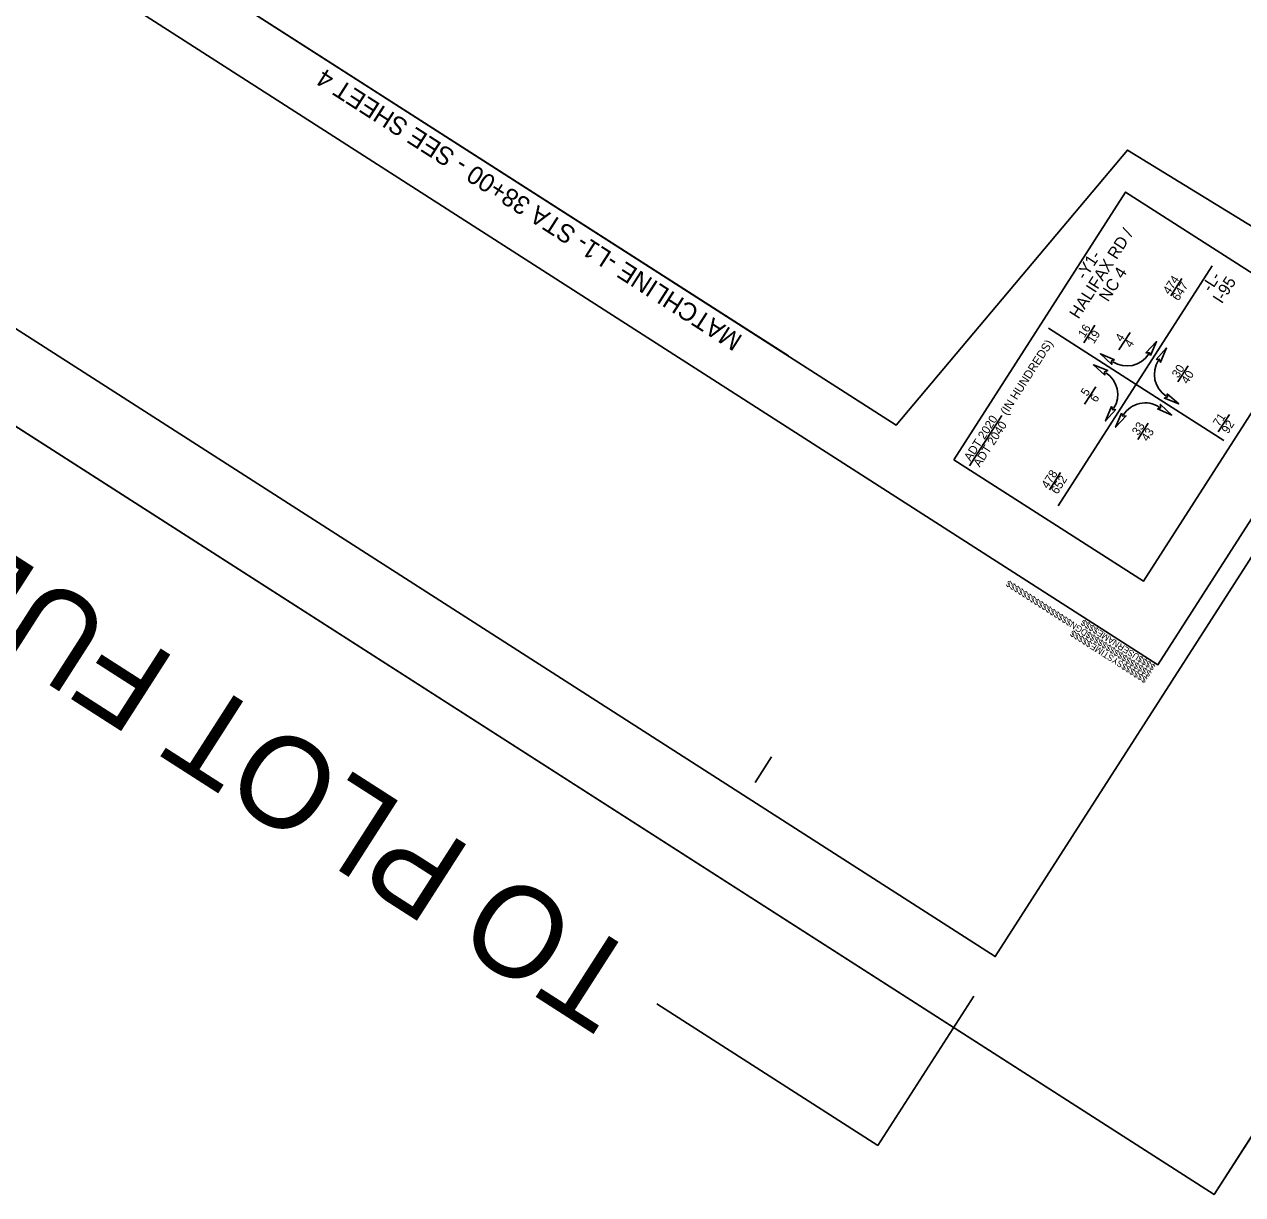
# Model space of a CAD drawing. Extents: x 2346049 to 2349719, y 842061 to 846435.
# Drawn here: x 2346919 to 2347924, y 842199 to 843164 of the extents above; entities that cross this region are included whole.
import ezdxf

# ---------------------------------------------------------------- set-up
doc = ezdxf.new("R2010")
doc.units = 0
for name, color, linetype in [('Default', 7, 'Continuous'), ('Matchline', 7, 'Continuous'), ('Matchline Text', 7, 'Continuous'), ('Prop DSN Text', 7, 'Continuous'), ('Scratch_Level_0', 7, 'Continuous'), ('Sheet Cutting Line CELL', 7, 'Continuous'), ('Sheet Detail CELL', 7, 'Continuous'), ('Sheet Plot Border Inside CELL', 7, 'Continuous'), ('Sheet Plot Border Outside CELL', 7, 'Continuous')]:
    doc.layers.add(name, color=color, linetype=linetype)

msp = doc.modelspace()

# ---------------------------------------------------------------- linework, layer by layer
at = {"layer": 'Default'}
for points in [[(2347848, 842891.1), (2347853, 842902.7), (2347844.3, 842893.4), (2347847.1, 842893.5)], [(2347818.4, 842887.6), (2347806.7, 842892.6), (2347816, 842883.9), (2347815.9, 842886.7)], [(2347852.7, 842888), (2347861.2, 842897.5), (2347856.3, 842885.7), (2347855.3, 842888.3)], [(2347810.4, 842875), (2347800.9, 842883.5), (2347812.7, 842878.7), (2347810.1, 842877.6)], [(2347853.8, 842847.2), (2347865.5, 842842.1), (2347856.2, 842850.8), (2347856.3, 842848)], [(2347861.9, 842859.7), (2347871.3, 842851.2), (2347859.5, 842856), (2347862.1, 842857.1)], [(2347819.5, 842846.7), (2347811, 842837.3), (2347815.9, 842849), (2347816.9, 842846.4)], [(2347824.2, 842843.7), (2347819.2, 842832), (2347827.9, 842841.3), (2347825.1, 842841.2)]]:
    msp.add_lwpolyline(points, close=True, dxfattribs=at)
for centre, start, end in [((2347828.5, 842904), 237.3281, 327.3281), ((2347872.6, 842875.7), 147.3282, 237.3282), ((2347799.6, 842859), 327.3282, 57.3282), ((2347843.7, 842830.7), 57.3281, 147.3281)]:
    msp.add_arc(centre, 21.4, start, end, dxfattribs=at)
at = {"layer": 'Matchline'}
msp.add_line((2347080.7, 843191.4), (2347549.3, 842890.9), dxfattribs=at)
at = {"layer": 'Prop DSN Text'}
for p, q in [((2347771.9, 842767.3), (2347898.8, 842965.1)), ((2347864.8, 842940.5), (2347874, 842954.8)), ((2347763.9, 842913.8), (2347836.2, 842867.4)), ((2347792.9, 842901.7), (2347802.1, 842916.1)), ((2347822, 842896), (2347831.2, 842910.3)), ((2347870.5, 842869.6), (2347879, 842882.8)), ((2347793.6, 842851.1), (2347802.8, 842865.4)), ((2347836.2, 842867.4), (2347908.4, 842821.1)), ((2347698.8, 842800.1), (2347725.4, 842841.6)), ((2347903.9, 842828.1), (2347913.1, 842842.5)), ((2347837.6, 842822), (2347846.1, 842835.3)), ((2347764.6, 842780.4), (2347773.8, 842794.7))]:
    msp.add_line(p, q, dxfattribs=at)
msp.add_lwpolyline([(2347685.9, 842805.1), (2347827.5, 843026), (2347983.9, 842925.8), (2347842.2, 842704.9)], close=True, dxfattribs=at)
at = {"layer": 'Scratch_Level_0'}
for points in [[(2349350.4, 845074.8), (2348851.8, 844297.2), (2348757.8, 844341), (2348462.4, 843706.5), (2348375.3, 843541.3), (2348255.5, 843353.8), (2348231.9, 843354.7), (2348207.8, 843279), (2348000.9, 842955.2), (2347829, 843060.7), (2347638.3, 842833.8), (2347080.7, 843191.4), (2347008.6, 843443.9), (2347324.8, 843936.9), (2346937.8, 844263.6), (2347160.2, 844610.4)], [(2349350.4, 845074.8), (2348851.8, 844297.2), (2348757.8, 844341), (2348462.4, 843706.5), (2348375.3, 843541.3), (2348255.5, 843353.8), (2348231.9, 843354.7), (2348207.8, 843279), (2348000.9, 842955.2), (2347829, 843060.7), (2347638.3, 842833.8), (2347080.7, 843191.4), (2347008.6, 843443.9), (2347324.8, 843936.9), (2346961.1, 844244), (2347005, 844312.5), (2347188.2, 844598.2)], [(2349350.4, 845074.8), (2348851.8, 844297.2), (2348757.8, 844341), (2348462.4, 843706.5), (2348375.3, 843541.3), (2348255.5, 843353.8), (2348231.9, 843354.7), (2348207.8, 843279), (2348000.9, 842955.2), (2347829, 843060.7), (2347638.3, 842833.8), (2347080.7, 843191.4), (2347008.6, 843443.9), (2347324.8, 843936.9), (2346961.1, 844244), (2347005, 844312.5), (2347188.2, 844598.2)]]:
    msp.add_lwpolyline(points, dxfattribs=at)
at = {"layer": 'Sheet Cutting Line CELL'}
for p, q in [((2347900.5, 842198.8), (2349718.7, 845033.9)), ((2347900.5, 842198.8), (2349718.7, 845033.9)), ((2346048.7, 843386.4), (2347900.5, 842198.8))]:
    msp.add_line(p, q, dxfattribs=at)
at = {"layer": 'Sheet Detail CELL'}
for p, q in [((2347522, 842539), (2347535.5, 842560)), ((2347702.2, 842362.5), (2347623.2, 842239.4)), ((2347440.8, 842356.3), (2347623.2, 842239.4))]:
    msp.add_line(p, q, dxfattribs=at)
msp.add_lwpolyline([(2346465.3, 843526.7), (2348084.7, 846052), (2349473.7, 845161.3), (2347854.2, 842636)], close=True, dxfattribs=at)
msp.add_lwpolyline([(2347874.4, 842667.6), (2347874.4, 842667.6)], dxfattribs=at)
at = {"layer": 'Sheet Plot Border Inside CELL'}
msp.add_lwpolyline([(2348083.9, 846082.3), (2346302.5, 843304.4), (2347720, 842395.3), (2349501.5, 845173.2)], close=True, dxfattribs=at)
at = {"layer": 'Sheet Plot Border Outside CELL'}
msp.add_lwpolyline([(2347866.8, 846221.5), (2346048.7, 843386.4), (2347900.5, 842198.8), (2349718.7, 845033.9)], close=True, dxfattribs=at)

# ---------------------------------------------------------------- texts
at = {"layer": 'Matchline Text'}
msp.add_text('MATCHLINE -L1- STA 38+00 - SEE SHEET 4', height=15, rotation=147.3281, dxfattribs=at).set_placement((2347512.4, 842906.8))
at = {"layer": 'Prop DSN Text'}
for s, height, p in [('HALIFAX RD / ', 9.8, (2347788.6, 842920.7)), ('-Y1-', 9.8, (2347794.1, 842953)), ('NC 4', 9.8, (2347813, 842934.9)), ('474', 7, (2347863.6, 842941.1)), ('647', 7, (2347871.1, 842935.8)), ('-L-', 9.8, (2347897.8, 842942.9)), ('I-95', 9.8, (2347906.9, 842933.3)), ('16', 7, (2347793.5, 842905.3)), ('19', 7, (2347801.3, 842900.4)), ('(IN HUNDREDS)', 7, (2347729.5, 842841.4)), ('4', 7, (2347824.3, 842902)), ('4', 7, (2347832, 842897.1)), ('30', 7, (2347870.9, 842872.1)), ('40', 7, (2347878.6, 842867.2)), ('5', 7, (2347795.8, 842857.1)), ('6', 7, (2347803.4, 842852)), ('ADT 2020', 7, (2347699.5, 842803.5)), ('71', 7, (2347904.8, 842832)), ('ADT 2040', 7, (2347707.2, 842798.6)), ('33', 7, (2347838, 842824.7)), ('43', 7, (2347845.7, 842819.8)), ('92', 7, (2347912, 842826.2)), ('478', 7, (2347763.3, 842780.8)), ('652', 7, (2347771.2, 842776.2))]:
    msp.add_text(s, height=height, rotation=57.3281, dxfattribs=at).set_placement(p)
at = {"layer": 'Sheet Detail CELL'}
for s, height, p in [('TO PLOT FULL SIZE 66"X34"', 75, (2347431, 842393.3)), ('$$$$$$$$$$$$$$$$DGN$$$$$$$$$$$$$$$$', 5.25, (2347849.4, 842630)), ('$$$$USERNAME$$$$', 5.25, (2347852.6, 842635.4)), ('$$$$$$SYSTIME$$$$$', 5.25, (2347846, 842625))]:
    msp.add_text(s, height=height, rotation=147.3281, dxfattribs=at).set_placement(p)

doc.saveas('drawing.dxf')
